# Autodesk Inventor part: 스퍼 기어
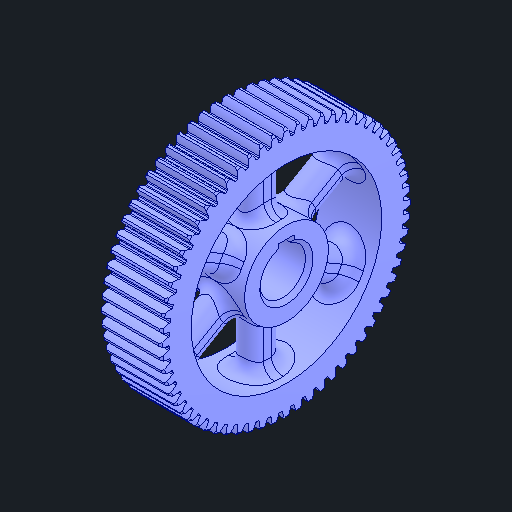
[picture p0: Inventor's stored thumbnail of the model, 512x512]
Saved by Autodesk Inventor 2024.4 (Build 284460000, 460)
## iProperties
Created: 2026-03
Part Number: 스퍼 기어
Material: 강철, 합금
Document SubType Name: Modeling
Designer: user
Density: 7.73 g/cm^3
Appearance: 기본값
Author: jhkim
Sending System: Autodesk Inventor 2026
Preprocessor: ST-DEVELOPER v20.1
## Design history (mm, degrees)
feature "솔리드1"
node "솔리드2"
